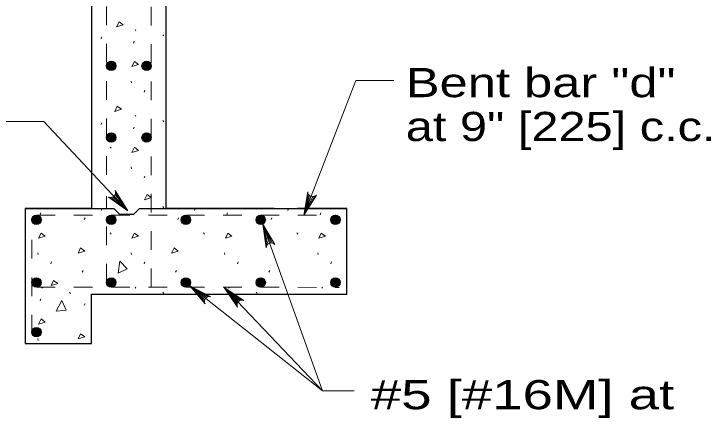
# Model space of a CAD drawing. Extents: x 1083.1 to 1117.1, y 697.4 to 743.4.
# Drawn here: x 1102.766 to 1106.498, y 724.26 to 726.421 of the extents above; entities that cross this region are included whole.
import ezdxf

# ---------------------------------------------------------------- set-up
doc = ezdxf.new("R2010")
doc.units = 0
doc.header["$LTSCALE"] = 0.064
doc.linetypes.add('SHORT_DASHED', pattern=[2.7, 1.5, -1.2])
doc.layers.add('1', color=7, linetype='Continuous', lineweight=13)

msp = doc.modelspace()

# ---------------------------------------------------------------- linework, layer by layer
at = {"layer": '1', "linetype": 'SHORT_DASHED'}
for p, q in [((1103.262, 725.56125), (1103.26217, 727.6815)), ((1103.50183, 724.95925), (1103.50183, 727.66992)), ((1103.26192, 724.98417), (1103.26192, 725.44717)), ((1102.86175, 724.71242), (1102.86183, 725.32008)), ((1102.88683, 725.34492), (1104.48908, 725.34492)), ((1102.88675, 724.95925), (1104.50792, 724.959))]:
    msp.add_line(p, q, dxfattribs=at)
at = {"layer": '1'}
for p, q in [((1103.4145, 726.33808), (1103.419, 726.33142)), ((1103.23308, 726.28808), (1103.2375, 726.29808)), ((1103.564, 726.30983), (1103.56842, 726.30317)), ((1103.40617, 726.26492), (1103.41058, 726.27492)), ((1103.28192, 726.16842), (1103.28633, 726.16175)), ((1103.394, 726.062), (1103.39517, 726.05208)), ((1103.46325, 726.00308), (1103.46767, 726.01308)), ((1103.4145, 725.87892), (1103.419, 725.87225)), ((1103.23308, 725.82892), (1103.2375, 725.83892)), ((1103.564, 725.85067), (1103.56842, 725.844)), ((1103.40617, 725.80583), (1103.41058, 725.81575)), ((1103.28192, 725.70925), (1103.28633, 725.70258)), ((1103.394, 725.60283), (1103.39517, 725.59292)), ((1103.46325, 725.544), (1103.46767, 725.554)), ((1103.31067, 725.46333), (1103.37608, 725.36783)), ((1103.28725, 725.43958), (1103.37608, 725.36783)), ((1103.2955, 725.44208), (1103.37608, 725.36783)), ((1103.30208, 725.44667), (1103.37608, 725.36783)), ((1103.30825, 725.45517), (1103.37608, 725.36783)), ((1104.34342, 725.45608), (1104.31808, 725.34475)), ((1104.34933, 725.44975), (1104.31808, 725.34475)), ((1104.35642, 725.44575), (1104.31808, 725.34475)), ((1104.375, 725.44558), (1104.31808, 725.34475)), ((1104.36658, 725.444), (1104.31808, 725.34475)), ((1103.564, 725.3915), (1103.56842, 725.38483)), ((1102.90642, 725.34667), (1102.91083, 725.35667)), ((1103.23308, 725.36983), (1103.2375, 725.37975)), ((1103.73283, 725.36983), (1103.73725, 725.37975)), ((1103.90592, 725.34667), (1103.91033, 725.35667)), ((1104.23258, 725.36983), (1104.237, 725.37975)), ((1104.40567, 725.34667), (1104.41008, 725.35667)), ((1103.14317, 725.32117), (1103.14758, 725.33117)), ((1103.643, 725.32117), (1103.64742, 725.33117)), ((1104.14275, 725.32117), (1104.14717, 725.33117)), ((1104.134, 725.19475), (1104.09817, 725.29683)), ((1104.12517, 725.1895), (1104.09817, 725.29683)), ((1104.11967, 725.183), (1104.09817, 725.29683)), ((1104.142, 725.19633), (1104.09817, 725.29683)), ((1104.15067, 725.19542), (1104.09817, 725.29683)), ((1104.09817, 725.29683), (1104.41817, 724.40533)), ((1103.28192, 725.25008), (1103.28633, 725.24342)), ((1103.78167, 725.25008), (1103.78608, 725.24342)), ((1104.28142, 725.25008), (1104.28583, 725.24342)), ((1102.89425, 725.14375), (1102.89542, 725.13375)), ((1103.394, 725.14375), (1103.39517, 725.13375)), ((1103.89375, 725.14375), (1103.89492, 725.13375)), ((1104.3935, 725.14375), (1104.39467, 725.13375)), ((1102.96342, 725.08492), (1102.96783, 725.09483)), ((1103.46325, 725.08492), (1103.46767, 725.09483)), ((1103.963, 725.08492), (1103.96742, 725.09483)), ((1104.46275, 725.08492), (1104.46717, 725.09483)), ((1103.13208, 725.03933), (1103.1365, 725.04933)), ((1103.63183, 725.03933), (1103.63633, 725.04933)), ((1104.13158, 725.03933), (1104.13608, 725.04933)), ((1102.91475, 724.96058), (1102.91925, 724.95392)), ((1103.4145, 724.96058), (1103.419, 724.95392)), ((1103.79217, 724.89992), (1103.70733, 724.96708)), ((1103.78742, 724.89075), (1103.70733, 724.96708)), ((1103.78633, 724.88225), (1103.70733, 724.96708)), ((1103.798, 724.90558), (1103.70733, 724.96708)), ((1103.80583, 724.90933), (1103.70733, 724.96708)), ((1103.70733, 724.96708), (1104.41817, 724.40533)), ((1103.96833, 724.88258), (1103.89183, 724.959)), ((1103.9625, 724.87408), (1103.89183, 724.959)), ((1103.9605, 724.86575), (1103.89183, 724.959)), ((1103.97483, 724.88742), (1103.89183, 724.959)), ((1103.98308, 724.89033), (1103.89183, 724.959)), ((1103.89183, 724.959), (1104.41817, 724.40533)), ((1103.91425, 724.96058), (1103.91875, 724.95392)), ((1104.414, 724.96058), (1104.4185, 724.95392)), ((1103.06425, 724.93242), (1103.06867, 724.92575)), ((1103.564, 724.93242), (1103.56842, 724.92575)), ((1104.06375, 724.93242), (1104.06817, 724.92575)), ((1102.90642, 724.8875), (1102.91083, 724.8975)), ((1103.14317, 724.862), (1103.14758, 724.872)), ((1102.89425, 724.68458), (1102.89542, 724.67458)), ((1104.41817, 724.40533), (1104.58775, 724.40533))]:
    msp.add_line(p, q, dxfattribs=at)
at = {"layer": '1', "lineweight": 25}
for p, q in [((1102.82575, 725.381), (1103.30092, 725.381)), ((1103.33083, 725.35092), (1103.30092, 725.381)), ((1103.33083, 725.35092), (1103.409, 725.351)), ((1103.43917, 725.381), (1103.409, 725.351)), ((1103.43917, 725.381), (1104.54842, 725.38092)), ((1104.16, 725.381), (1103.582, 725.381)), ((1104.54842, 725.38092), (1104.28358, 725.381)), ((1104.54842, 724.92325), (1104.54842, 725.38092))]:
    msp.add_line(p, q, dxfattribs=at)
for points in [[(1103.18175, 727.736), (1103.18175, 727.54658), (1103.18175, 727.29658), (1103.18175, 726.48833), (1103.18175, 725.38092)], [(1103.582, 725.38217), (1103.582, 727.02233), (1103.582, 727.73592)], [(1103.18175, 725.38092), (1102.82575, 725.381), (1102.82575, 724.65883), (1103.18175, 724.65883), (1103.18175, 724.92325)], [(1103.18175, 724.92325), (1104.02675, 724.92325), (1104.54842, 724.92325)]]:
    msp.add_lwpolyline(points, dxfattribs=at)
at = {"layer": '1'}
for points in [[(1103.3155, 726.35158), (1103.32883, 726.37933), (1103.351, 726.36267)], [(1103.39833, 726.13958), (1103.41167, 726.16733), (1103.43392, 726.15067)], [(1103.30608, 725.9), (1103.31942, 725.92775), (1103.34167, 725.91108)], [(1103.39833, 725.68042), (1103.41167, 725.70817), (1103.43392, 725.6915)], [(1103.46542, 725.4275), (1103.47875, 725.45525), (1103.50092, 725.43858)], [(1102.89858, 725.22133), (1102.91192, 725.249), (1102.93417, 725.23242)], [(1103.39833, 725.22133), (1103.41167, 725.249), (1103.43392, 725.23242)], [(1103.89808, 725.22133), (1103.91142, 725.249), (1103.93367, 725.23242)], [(1104.39783, 725.22133), (1104.41117, 725.249), (1104.43342, 725.23242)], [(1103.11017, 725.142), (1103.1235, 725.16975), (1103.14558, 725.15308)], [(1103.60992, 725.142), (1103.62325, 725.16975), (1103.64542, 725.15308)], [(1102.96558, 724.96833), (1102.97892, 724.99608), (1103.00117, 724.97942)], [(1104.46492, 724.96833), (1104.47825, 724.99608), (1104.5005, 724.97942)], [(1102.89858, 724.76217), (1102.91192, 724.78992), (1102.93417, 724.77325)], [(1103.11017, 724.68283), (1103.1235, 724.71058), (1103.14558, 724.69392)]]:
    msp.add_lwpolyline(points, close=True, dxfattribs=at)
for points in [[(1104.31808, 725.34475), (1104.59583, 726.06475), (1104.8, 726.06475)], [(1103.37033, 725.37217), (1102.92683, 725.84642), (1102.15325, 725.84642)], [(1103.30883, 725.47617), (1103.37608, 725.36783), (1103.2725, 725.442)], [(1104.38567, 725.45267), (1104.31808, 725.34475), (1104.33892, 725.47042)], [(1104.11617, 725.17067), (1104.09817, 725.29683), (1104.16317, 725.18733)], [(1103.32367, 725.035), (1103.3325, 725.09833), (1103.37217, 725.05733), (1103.32467, 725.03533)], [(1103.78983, 724.86992), (1103.70733, 724.96708), (1103.82083, 724.90908)], [(1103.96258, 724.853), (1103.89183, 724.959), (1103.99792, 724.88842)], [(1102.99333, 724.832), (1103.02333, 724.88858), (1103.04667, 724.8365), (1102.9945, 724.832)]]:
    msp.add_lwpolyline(points, dxfattribs=at)
at = {"layer": '1', "lineweight": 25}
for centre, major_axis in [((1103.28697, 726.14277), (0.02499, 0)), ((1103.28697, 726.14277), (0.02499, 0)), ((1103.28697, 726.14277), (0.02077, 0)), ((1103.28697, 726.14277), (0.01726, 0)), ((1103.28697, 726.14277), (0.01434, 0)), ((1103.28697, 726.14277), (0.01192, 0)), ((1103.28697, 726.14277), (0.0099, 0)), ((1103.28697, 726.14277), (0.00823, 0)), ((1103.28697, 726.14277), (0.00684, 0)), ((1103.28697, 726.14277), (0.00568, 0)), ((1103.28697, 726.14277), (0.00472, 0)), ((1103.28697, 726.14277), (0.00392, 0)), ((1103.28697, 726.14277), (0.00326, 0)), ((1103.28697, 726.14277), (0.00271, 0)), ((1103.28697, 726.14277), (0.00225, 0)), ((1103.28697, 726.14277), (0.00187, 0)), ((1103.47688, 726.14277), (0.02499, 0)), ((1103.47688, 726.14277), (0.02499, 0)), ((1103.47688, 726.14277), (0.02077, 0)), ((1103.47688, 726.14277), (0.01726, 0)), ((1103.47688, 726.14277), (0.01434, 0)), ((1103.47688, 726.14277), (0.01192, 0)), ((1103.47688, 726.14277), (0.0099, 0)), ((1103.47688, 726.14277), (0.00823, 0)), ((1103.47688, 726.14277), (0.00684, 0)), ((1103.47688, 726.14277), (0.00568, 0)), ((1103.47688, 726.14277), (0.00472, 0)), ((1103.47688, 726.14277), (0.00392, 0)), ((1103.47688, 726.14277), (0.00326, 0)), ((1103.47688, 726.14277), (0.00271, 0)), ((1103.47688, 726.14277), (0.00225, 0)), ((1103.47688, 726.14277), (0.00187, 0)), ((1103.28697, 725.75957), (0.02499, 0)), ((1103.28697, 725.75957), (0.02499, 0)), ((1103.28697, 725.75957), (0.02077, 0)), ((1103.28697, 725.75957), (0.01726, 0)), ((1103.28697, 725.75957), (0.01434, 0)), ((1103.28697, 725.75957), (0.01192, 0)), ((1103.28697, 725.75957), (0.0099, 0)), ((1103.28697, 725.75957), (0.00823, 0)), ((1103.28697, 725.75957), (0.00684, 0)), ((1103.28697, 725.75957), (0.00568, 0)), ((1103.28697, 725.75957), (0.00472, 0)), ((1103.28697, 725.75957), (0.00392, 0)), ((1103.28697, 725.75957), (0.00326, 0)), ((1103.28697, 725.75957), (0.00271, 0)), ((1103.28697, 725.75957), (0.00225, 0)), ((1103.28697, 725.75957), (0.00187, 0)), ((1103.47688, 725.75957), (0.02499, 0)), ((1103.47688, 725.75957), (0.02499, 0)), ((1103.47688, 725.75957), (0.02077, 0)), ((1103.47688, 725.75957), (0.01726, 0)), ((1103.47688, 725.75957), (0.01434, 0)), ((1103.47688, 725.75957), (0.01192, 0)), ((1103.47688, 725.75957), (0.0099, 0)), ((1103.47688, 725.75957), (0.00823, 0)), ((1103.47688, 725.75957), (0.00684, 0)), ((1103.47688, 725.75957), (0.00568, 0)), ((1103.47688, 725.75957), (0.00472, 0)), ((1103.47688, 725.75957), (0.00392, 0)), ((1103.47688, 725.75957), (0.00326, 0)), ((1103.47688, 725.75957), (0.00271, 0)), ((1103.47688, 725.75957), (0.00225, 0)), ((1103.47688, 725.75957), (0.00187, 0)), ((1102.88683, 725.31991), (0.02499, 0)), ((1102.88683, 725.31991), (0.02499, 0)), ((1102.88683, 725.31991), (0.02077, 0)), ((1102.88683, 725.31991), (0.01726, 0)), ((1102.88683, 725.31991), (0.01434, 0)), ((1102.88683, 725.31991), (0.01192, 0)), ((1102.88683, 725.31991), (0.0099, 0)), ((1102.88683, 725.31991), (0.00823, 0)), ((1102.88683, 725.31991), (0.00684, 0)), ((1102.88683, 725.31991), (0.00568, 0)), ((1102.88683, 725.31991), (0.00472, 0)), ((1102.88683, 725.31991), (0.00392, 0)), ((1102.88683, 725.31991), (0.00326, 0)), ((1102.88683, 725.31991), (0.00271, 0)), ((1102.88683, 725.31991), (0.00225, 0)), ((1102.88683, 725.31991), (0.00187, 0)), ((1103.28697, 725.31991), (0.02499, 0)), ((1103.28697, 725.31991), (0.02499, 0)), ((1103.28697, 725.31991), (0.02077, 0)), ((1103.28697, 725.31991), (0.01726, 0)), ((1103.28697, 725.31991), (0.01434, 0)), ((1103.28697, 725.31991), (0.01192, 0)), ((1103.28697, 725.31991), (0.0099, 0)), ((1103.28697, 725.31991), (0.00823, 0)), ((1103.28697, 725.31991), (0.00684, 0)), ((1103.28697, 725.31991), (0.00568, 0)), ((1103.28697, 725.31991), (0.00472, 0)), ((1103.28697, 725.31991), (0.00392, 0)), ((1103.28697, 725.31991), (0.00326, 0)), ((1103.28697, 725.31991), (0.00271, 0)), ((1103.28697, 725.31991), (0.00225, 0)), ((1103.28697, 725.31991), (0.00187, 0)), ((1103.68712, 725.31991), (0.02499, 0)), ((1103.68712, 725.31991), (0.02499, 0)), ((1103.68712, 725.31991), (0.02077, 0)), ((1103.68712, 725.31991), (0.01726, 0)), ((1103.68712, 725.31991), (0.01434, 0)), ((1103.68712, 725.31991), (0.01192, 0)), ((1103.68712, 725.31991), (0.0099, 0)), ((1103.68712, 725.31991), (0.00823, 0)), ((1103.68712, 725.31991), (0.00684, 0)), ((1103.68712, 725.31991), (0.00568, 0)), ((1103.68712, 725.31991), (0.00472, 0)), ((1103.68712, 725.31991), (0.00392, 0)), ((1103.68712, 725.31991), (0.00326, 0)), ((1103.68712, 725.31991), (0.00271, 0)), ((1103.68712, 725.31991), (0.00225, 0)), ((1103.68712, 725.31991), (0.00187, 0)), ((1104.08726, 725.31991), (0.02499, 0)), ((1104.08726, 725.31991), (0.02499, 0)), ((1104.08726, 725.31991), (0.02077, 0)), ((1104.08726, 725.31991), (0.01726, 0)), ((1104.08726, 725.31991), (0.01434, 0)), ((1104.08726, 725.31991), (0.01192, 0)), ((1104.08726, 725.31991), (0.0099, 0)), ((1104.08726, 725.31991), (0.00823, 0)), ((1104.08726, 725.31991), (0.00684, 0)), ((1104.08726, 725.31991), (0.00568, 0)), ((1104.08726, 725.31991), (0.00472, 0)), ((1104.08726, 725.31991), (0.00392, 0)), ((1104.08726, 725.31991), (0.00326, 0)), ((1104.08726, 725.31991), (0.00271, 0)), ((1104.08726, 725.31991), (0.00225, 0)), ((1104.08726, 725.31991), (0.00187, 0)), ((1104.48732, 725.31991), (0.02499, 0)), ((1104.48732, 725.31991), (0.02499, 0)), ((1104.48732, 725.31991), (0.02077, 0)), ((1104.48732, 725.31991), (0.01726, 0)), ((1104.48732, 725.31991), (0.01434, 0)), ((1104.48732, 725.31991), (0.01192, 0)), ((1104.48732, 725.31991), (0.0099, 0)), ((1104.48732, 725.31991), (0.00823, 0)), ((1104.48732, 725.31991), (0.00684, 0)), ((1104.48732, 725.31991), (0.00568, 0)), ((1104.48732, 725.31991), (0.00472, 0)), ((1104.48732, 725.31991), (0.00392, 0)), ((1104.48732, 725.31991), (0.00326, 0)), ((1104.48732, 725.31991), (0.00271, 0)), ((1104.48732, 725.31991), (0.00225, 0)), ((1104.48732, 725.31991), (0.00187, 0)), ((1102.88683, 724.98427), (0.02499, 0)), ((1102.88683, 724.98427), (0.02499, 0)), ((1102.88683, 724.98427), (0.02077, 0)), ((1102.88683, 724.98427), (0.01726, 0)), ((1102.88683, 724.98427), (0.01434, 0)), ((1102.88683, 724.98427), (0.01192, 0)), ((1102.88683, 724.98427), (0.0099, 0)), ((1102.88683, 724.98427), (0.00823, 0)), ((1102.88683, 724.98427), (0.00684, 0)), ((1102.88683, 724.98427), (0.00568, 0)), ((1102.88683, 724.98427), (0.00472, 0)), ((1102.88683, 724.98427), (0.00392, 0)), ((1102.88683, 724.98427), (0.00326, 0)), ((1102.88683, 724.98427), (0.00271, 0)), ((1102.88683, 724.98427), (0.00225, 0)), ((1102.88683, 724.98427), (0.00187, 0)), ((1103.28697, 724.98427), (0.02499, 0)), ((1103.28697, 724.98427), (0.02499, 0)), ((1103.28697, 724.98427), (0.02077, 0)), ((1103.28697, 724.98427), (0.01726, 0)), ((1103.28697, 724.98427), (0.01434, 0)), ((1103.28697, 724.98427), (0.01192, 0)), ((1103.28697, 724.98427), (0.0099, 0)), ((1103.28697, 724.98427), (0.00823, 0)), ((1103.28697, 724.98427), (0.00684, 0)), ((1103.28697, 724.98427), (0.00568, 0)), ((1103.28697, 724.98427), (0.00472, 0)), ((1103.28697, 724.98427), (0.00392, 0)), ((1103.28697, 724.98427), (0.00326, 0)), ((1103.28697, 724.98427), (0.00271, 0)), ((1103.28697, 724.98427), (0.00225, 0)), ((1103.28697, 724.98427), (0.00187, 0)), ((1103.68712, 724.98427), (0.02499, 0)), ((1103.68712, 724.98427), (0.02499, 0)), ((1103.68712, 724.98427), (0.02077, 0)), ((1103.68712, 724.98427), (0.01726, 0)), ((1103.68712, 724.98427), (0.01434, 0)), ((1103.68712, 724.98427), (0.01192, 0)), ((1103.68712, 724.98427), (0.0099, 0)), ((1103.68712, 724.98427), (0.00823, 0)), ((1103.68712, 724.98427), (0.00684, 0)), ((1103.68712, 724.98427), (0.00568, 0)), ((1103.68712, 724.98427), (0.00472, 0)), ((1103.68712, 724.98427), (0.00392, 0)), ((1103.68712, 724.98427), (0.00326, 0)), ((1103.68712, 724.98427), (0.00271, 0)), ((1103.68712, 724.98427), (0.00225, 0)), ((1103.68712, 724.98427), (0.00187, 0)), ((1104.08726, 724.98427), (0.02499, 0)), ((1104.08726, 724.98427), (0.02499, 0)), ((1104.08726, 724.98427), (0.02077, 0)), ((1104.08726, 724.98427), (0.01726, 0)), ((1104.08726, 724.98427), (0.01434, 0)), ((1104.08726, 724.98427), (0.01192, 0)), ((1104.08726, 724.98427), (0.0099, 0)), ((1104.08726, 724.98427), (0.00823, 0)), ((1104.08726, 724.98427), (0.00684, 0)), ((1104.08726, 724.98427), (0.00568, 0)), ((1104.08726, 724.98427), (0.00472, 0)), ((1104.08726, 724.98427), (0.00392, 0)), ((1104.08726, 724.98427), (0.00326, 0)), ((1104.08726, 724.98427), (0.00271, 0)), ((1104.08726, 724.98427), (0.00225, 0)), ((1104.08726, 724.98427), (0.00187, 0)), ((1104.48732, 724.98427), (0.02499, 0)), ((1104.48732, 724.98427), (0.02499, 0)), ((1104.48732, 724.98427), (0.02077, 0)), ((1104.48732, 724.98427), (0.01726, 0)), ((1104.48732, 724.98427), (0.01434, 0)), ((1104.48732, 724.98427), (0.01192, 0)), ((1104.48732, 724.98427), (0.0099, 0)), ((1104.48732, 724.98427), (0.00823, 0)), ((1104.48732, 724.98427), (0.00684, 0)), ((1104.48732, 724.98427), (0.00568, 0)), ((1104.48732, 724.98427), (0.00472, 0)), ((1104.48732, 724.98427), (0.00392, 0)), ((1104.48732, 724.98427), (0.00326, 0)), ((1104.48732, 724.98427), (0.00271, 0)), ((1104.48732, 724.98427), (0.00225, 0)), ((1104.48732, 724.98427), (0.00187, 0)), ((1102.88683, 724.71992), (0.02499, 0)), ((1102.88683, 724.71992), (0.02499, 0)), ((1102.88683, 724.71992), (0.02077, 0)), ((1102.88683, 724.71992), (0.01726, 0)), ((1102.88683, 724.71992), (0.01434, 0)), ((1102.88683, 724.71992), (0.01192, 0)), ((1102.88683, 724.71992), (0.0099, 0)), ((1102.88683, 724.71992), (0.00823, 0)), ((1102.88683, 724.71992), (0.00684, 0)), ((1102.88683, 724.71992), (0.00568, 0)), ((1102.88683, 724.71992), (0.00472, 0)), ((1102.88683, 724.71992), (0.00392, 0)), ((1102.88683, 724.71992), (0.00326, 0)), ((1102.88683, 724.71992), (0.00271, 0)), ((1102.88683, 724.71992), (0.00225, 0)), ((1102.88683, 724.71992), (0.00187, 0))]:
    msp.add_ellipse(centre, major_axis=major_axis, ratio=0.999895, dxfattribs=at)
at = {"layer": '1'}
for centre, major_axis, start_param, end_param in [((1103.28374, 725.46638), (-0.02697, 0), 1.1385704, 3.5091835), ((1104.3659, 725.47104), (-0.02697, 0), 0.0239449, 2.394558), ((1104.14303, 725.16939), (0.02446, -0.01136), 1.1586385, 3.5292516), ((1103.81329, 724.88322), (-0.0096, 0.0252), 5.6350249, 8.005638), ((1103.98739, 724.86357), (0.0268, -0.00302), 1.2833392, 3.6539523)]:
    msp.add_ellipse(centre, major_axis=major_axis, ratio=0.999895, start_param=start_param, end_param=end_param, dxfattribs=at)

# ---------------------------------------------------------------- texts
for s, width, p in [('Bent bar "d"', 1.3, (1104.864, 725.97583)), ('at 9" [225] c.c.', 1.25, (1104.864, 725.74117)), ('#5 [#16M] at', 1.4, (1104.67725, 724.30717))]:
    msp.add_text(s, height=0.156, dxfattribs=dict(at, width=width)).set_placement(p)

doc.saveas('drawing.dxf')
